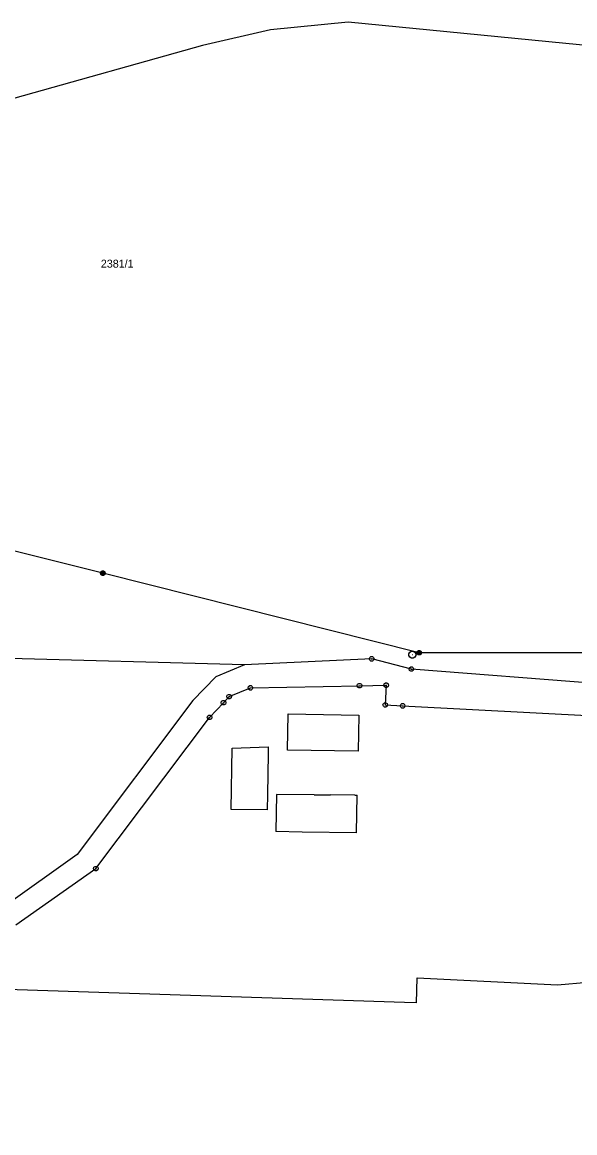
# Model space of a CAD drawing. Extents: x -760611 to -758411, y -1176479 to -1174807.
# Drawn here: x -758742.6 to -758625.1, y -1175353 to -1175117.1 of the extents above; entities that cross this region are included whole.
import ezdxf

# ---------------------------------------------------------------- set-up
doc = ezdxf.new("R2010")
doc.units = 0
for name, color, linetype in [('1', 7, 'Continuous'), ('11', 7, 'Continuous'), ('12', 7, 'Continuous'), ('2', 7, 'Continuous'), ('6', 7, 'Continuous'), ('8', 7, 'Continuous')]:
    doc.layers.add(name, color=color, linetype=linetype)

msp = doc.modelspace()

# ---------------------------------------------------------------- linework, layer by layer
at = {"layer": '1'}
for p, q in [((-758695.3, -1175253.59), (-758801.99, -1175250.69)), ((-758668.26, -1175252.33), (-758695.3, -1175253.59)), ((-758659.81, -1175254.52), (-758668.26, -1175252.33)), ((-758695.3, -1175253.59), (-758701.44, -1175256.15)), ((-758608.97, -1175258.5), (-758659.81, -1175254.52)), ((-758701.44, -1175256.15), (-758706.31, -1175261.2)), ((-758698.55, -1175260.36), (-758694.05, -1175258.49)), ((-758694.05, -1175258.49), (-758670.85, -1175258.03)), ((-758670.85, -1175258.03), (-758665.18, -1175257.92)), ((-758665.18, -1175257.92), (-758665.37, -1175262.13)), ((-758706.31, -1175261.2), (-758730.9, -1175293.88)), ((-758702.73, -1175264.76), (-758699.78, -1175261.65)), ((-758699.78, -1175261.65), (-758698.55, -1175260.36)), ((-758665.37, -1175262.13), (-758661.68, -1175262.32)), ((-758661.68, -1175262.32), (-758614.76, -1175264.74)), ((-758726.91, -1175296.89), (-758702.73, -1175264.76)), ((-758730.9, -1175293.88), (-758746.46, -1175305.02)), ((-758743.91, -1175308.85), (-758726.91, -1175296.89))]:
    msp.add_line(p, q, dxfattribs=at)
at = {"layer": '11'}
for points in [[(-758613.2, -1175122.93), (-758673.25, -1175117.07), (-758689.79, -1175118.68), (-758704.22, -1175121.99), (-758744.12, -1175133.22), (-758751.33, -1175134.45), (-758778.47, -1175135.16), (-758805.62, -1175139.26), (-758832.79, -1175148.43), (-758845.03, -1175153.89), (-758850.63, -1175156.38), (-758865.57, -1175161.54), (-758866.34, -1175161.81), (-758886.7, -1175164.24), (-758890.57, -1175164.29), (-758911.29, -1175164.54), (-758939.71, -1175166.52), (-758954.56, -1175170.25), (-758967.72, -1175174.84), (-758975.79, -1175178.19), (-758988.73, -1175187.68)], [(-758658.74, -1175325.4), (-758658.59, -1175320.08), (-758628.72, -1175321.59), (-758602.92, -1175319.32), (-758591.26, -1175316.24), (-758588.35, -1175311.33), (-758584.49, -1175300.82), (-758584.43, -1175300.74), (-758579.33, -1175293.56), (-758578.06, -1175297.48), (-758578.1, -1175299.22), (-758577.84, -1175300.51), (-758576.42, -1175307.68)], [(-758658.74, -1175325.4), (-758661.28, -1175325.32), (-758752.38, -1175322.35), (-758753.28, -1175322.32), (-758766.61, -1175320.84), (-758767.99, -1175317.35), (-758768.47, -1175316.14), (-758778.64, -1175314.83), (-758817.04, -1175324.96), (-758847.47, -1175336.66), (-758851.6, -1175338.92), (-758867.88, -1175347.8), (-758875.08, -1175351.73), (-758883.45, -1175352.34), (-758892.8, -1175353.02)]]:
    msp.add_lwpolyline(points, dxfattribs=at)
at = {"layer": '12'}
for p, q in [((-758686.15, -1175271.72), (-758686.01, -1175263.99)), ((-758686.01, -1175263.99), (-758670.97, -1175264.29)), ((-758670.97, -1175264.29), (-758671.12, -1175271.97)), ((-758698.17, -1175284.32), (-758697.93, -1175271.28)), ((-758697.93, -1175271.28), (-758690.26, -1175271.05)), ((-758690.27, -1175271.65), (-758690.29, -1175272.5)), ((-758690.26, -1175271.05), (-758690.27, -1175271.65)), ((-758690.29, -1175272.5), (-758690.45, -1175281.12)), ((-758671.12, -1175271.97), (-758686.15, -1175271.72)), ((-758690.45, -1175281.12), (-758690.51, -1175284.43)), ((-758688.53, -1175281.14), (-758688.65, -1175289.02)), ((-758680.52, -1175281.2), (-758688.53, -1175281.14)), ((-758680.52, -1175281.2), (-758677.01, -1175281.23)), ((-758671.84, -1175281.28), (-758677.01, -1175281.23)), ((-758671.84, -1175281.28), (-758671.34, -1175281.28)), ((-758671.48, -1175289.32), (-758671.34, -1175281.28)), ((-758690.51, -1175284.43), (-758698.17, -1175284.32)), ((-758683.07, -1175289.13), (-758688.65, -1175289.02)), ((-758671.48, -1175289.32), (-758683.07, -1175289.13))]:
    msp.add_line(p, q, dxfattribs=at)
at = {"layer": '6'}
for p, q in [((-758725.44, -1175234.14), (-758788.97, -1175218.21)), ((-758658.17, -1175251.04), (-758725.44, -1175234.14)), ((-758583.89, -1175251.11), (-758658.17, -1175251.04))]:
    msp.add_line(p, q, dxfattribs=at)
for points in [[(-758725.59, -1175233.66), (-758725.28, -1175233.66), (-758725.03, -1175233.84), (-758724.93, -1175234.13), (-758725.03, -1175234.42), (-758725.28, -1175234.6), (-758725.59, -1175234.6), (-758725.84, -1175234.42), (-758725.94, -1175234.13), (-758725.84, -1175233.84), (-758725.59, -1175233.66), (-758725.56, -1175233.7), (-758725.32, -1175233.7), (-758725.16, -1175233.78), (-758725.72, -1175233.78), (-758725.8, -1175233.86), (-758725.08, -1175233.86), (-758725.08, -1175233.94), (-758725.8, -1175233.94), (-758725.84, -1175234.02), (-758725.04, -1175234.02), (-758725, -1175234.1), (-758725.88, -1175234.1), (-758725.88, -1175234.18), (-758725, -1175234.18), (-758725.03, -1175234.26), (-758725.84, -1175234.26), (-758725.83, -1175234.34), (-758725.02, -1175234.34), (-758725.07, -1175234.42), (-758725.79, -1175234.42), (-758725.71, -1175234.5), (-758725.15, -1175234.5), (-758725.26, -1175234.58), (-758725.6, -1175234.58)], [(-758658.32, -1175250.56), (-758658.01, -1175250.56), (-758657.76, -1175250.74), (-758657.66, -1175251.03), (-758657.76, -1175251.32), (-758658.01, -1175251.5), (-758658.32, -1175251.5), (-758658.57, -1175251.32), (-758658.67, -1175251.03), (-758658.57, -1175250.74), (-758658.32, -1175250.56), (-758658.29, -1175250.6), (-758658.05, -1175250.6), (-758657.89, -1175250.68), (-758658.45, -1175250.68), (-758658.53, -1175250.76), (-758657.81, -1175250.76), (-758657.81, -1175250.84), (-758658.53, -1175250.84), (-758658.57, -1175250.92), (-758657.77, -1175250.92), (-758657.73, -1175251), (-758658.61, -1175251), (-758658.61, -1175251.08), (-758657.73, -1175251.08), (-758657.76, -1175251.16), (-758658.57, -1175251.16), (-758658.56, -1175251.24), (-758657.75, -1175251.24), (-758657.8, -1175251.32), (-758658.52, -1175251.32), (-758658.44, -1175251.4), (-758657.88, -1175251.4), (-758657.99, -1175251.48), (-758658.33, -1175251.48)]]:
    msp.add_lwpolyline(points, dxfattribs=at)
at = {"layer": '8'}
for p, q in [((-758668.38, -1175252.33), (-758668.14, -1175252.33)), ((-758659.66, -1175251.42), (-758659.56, -1175251.42)), ((-758659.93, -1175254.52), (-758659.69, -1175254.52)), ((-758694.17, -1175258.49), (-758693.93, -1175258.49)), ((-758670.97, -1175258.03), (-758670.73, -1175258.03)), ((-758665.3, -1175257.92), (-758665.06, -1175257.92)), ((-758699.9, -1175261.65), (-758699.66, -1175261.65)), ((-758698.67, -1175260.36), (-758698.43, -1175260.36)), ((-758665.49, -1175262.13), (-758665.25, -1175262.13)), ((-758661.8, -1175262.32), (-758661.56, -1175262.32)), ((-758702.85, -1175264.76), (-758702.61, -1175264.76)), ((-758727.03, -1175296.89), (-758726.79, -1175296.89))]:
    msp.add_line(p, q, dxfattribs=at)
for points in [[(-758668.11, -1175251.85), (-758667.86, -1175252.03), (-758667.76, -1175252.32), (-758667.86, -1175252.61), (-758668.11, -1175252.79), (-758668.42, -1175252.79), (-758668.67, -1175252.61), (-758668.77, -1175252.32), (-758668.67, -1175252.03), (-758668.42, -1175251.85)], [(-758659.42, -1175250.7), (-758659.08, -1175250.89), (-758658.89, -1175251.23), (-758658.89, -1175251.62), (-758659.08, -1175251.96), (-758659.42, -1175252.15), (-758659.81, -1175252.15), (-758660.15, -1175251.96), (-758660.34, -1175251.62), (-758660.34, -1175251.23), (-758660.15, -1175250.89), (-758659.81, -1175250.7)], [(-758659.66, -1175254.04), (-758659.41, -1175254.22), (-758659.31, -1175254.51), (-758659.41, -1175254.8), (-758659.66, -1175254.98), (-758659.97, -1175254.98), (-758660.22, -1175254.8), (-758660.32, -1175254.51), (-758660.22, -1175254.22), (-758659.97, -1175254.04)], [(-758665.03, -1175257.44), (-758664.78, -1175257.62), (-758664.68, -1175257.91), (-758664.78, -1175258.2), (-758665.03, -1175258.38), (-758665.34, -1175258.38), (-758665.59, -1175258.2), (-758665.69, -1175257.91), (-758665.59, -1175257.62), (-758665.34, -1175257.44)], [(-758693.9, -1175258.01), (-758693.65, -1175258.19), (-758693.55, -1175258.48), (-758693.65, -1175258.77), (-758693.9, -1175258.95), (-758694.21, -1175258.95), (-758694.46, -1175258.77), (-758694.56, -1175258.48), (-758694.46, -1175258.19), (-758694.21, -1175258.01)], [(-758670.7, -1175257.55), (-758670.45, -1175257.73), (-758670.35, -1175258.02), (-758670.45, -1175258.31), (-758670.7, -1175258.49), (-758671.01, -1175258.49), (-758671.26, -1175258.31), (-758671.36, -1175258.02), (-758671.26, -1175257.73), (-758671.01, -1175257.55)], [(-758699.63, -1175261.17), (-758699.38, -1175261.35), (-758699.28, -1175261.64), (-758699.38, -1175261.93), (-758699.63, -1175262.11), (-758699.94, -1175262.11), (-758700.19, -1175261.93), (-758700.29, -1175261.64), (-758700.19, -1175261.35), (-758699.94, -1175261.17)], [(-758698.4, -1175259.88), (-758698.15, -1175260.06), (-758698.05, -1175260.35), (-758698.15, -1175260.64), (-758698.4, -1175260.82), (-758698.71, -1175260.82), (-758698.96, -1175260.64), (-758699.06, -1175260.35), (-758698.96, -1175260.06), (-758698.71, -1175259.88)], [(-758665.22, -1175261.65), (-758664.97, -1175261.83), (-758664.87, -1175262.12), (-758664.97, -1175262.41), (-758665.22, -1175262.59), (-758665.53, -1175262.59), (-758665.78, -1175262.41), (-758665.88, -1175262.12), (-758665.78, -1175261.83), (-758665.53, -1175261.65)], [(-758661.53, -1175261.84), (-758661.28, -1175262.02), (-758661.18, -1175262.31), (-758661.28, -1175262.6), (-758661.53, -1175262.78), (-758661.84, -1175262.78), (-758662.09, -1175262.6), (-758662.19, -1175262.31), (-758662.09, -1175262.02), (-758661.84, -1175261.84)], [(-758702.58, -1175264.28), (-758702.33, -1175264.46), (-758702.23, -1175264.75), (-758702.33, -1175265.04), (-758702.58, -1175265.22), (-758702.89, -1175265.22), (-758703.14, -1175265.04), (-758703.24, -1175264.75), (-758703.14, -1175264.46), (-758702.89, -1175264.28)], [(-758726.76, -1175296.41), (-758726.51, -1175296.59), (-758726.41, -1175296.88), (-758726.51, -1175297.17), (-758726.76, -1175297.35), (-758727.07, -1175297.35), (-758727.32, -1175297.17), (-758727.42, -1175296.88), (-758727.32, -1175296.59), (-758727.07, -1175296.41)]]:
    msp.add_lwpolyline(points, close=True, dxfattribs=at)

# ---------------------------------------------------------------- texts
at = {"layer": '2'}
msp.add_text('2381/1', height=1.7, dxfattribs=at).set_placement((-758725.85, -1175169.22))

doc.saveas('drawing.dxf')
